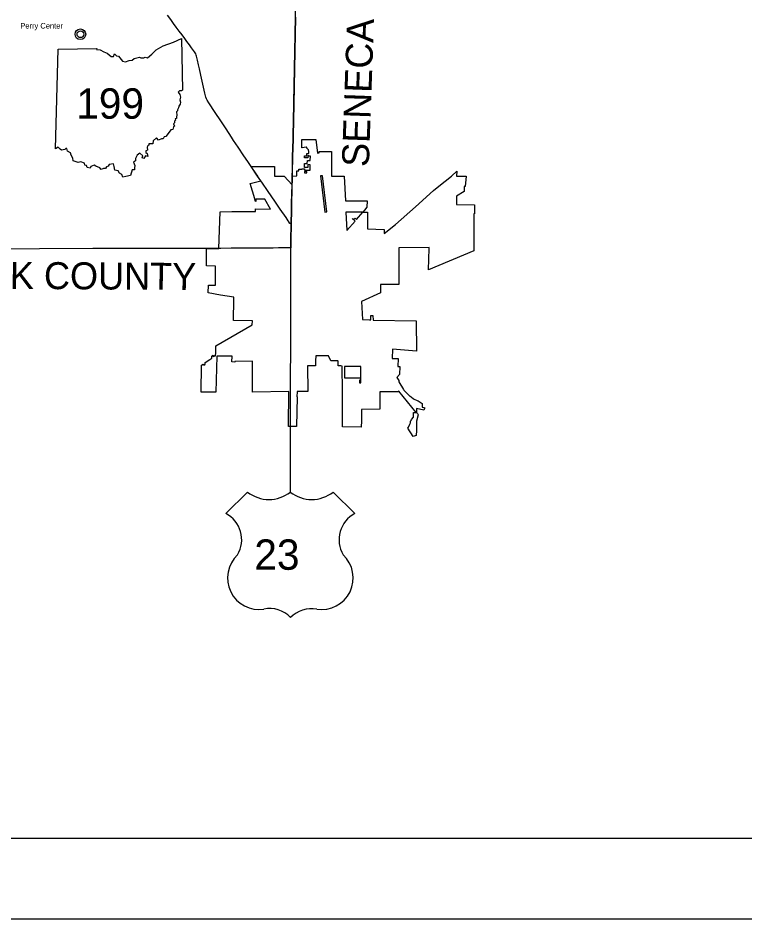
# Model space of a CAD drawing. Extents: x 0 to 851, y 0 to 440.
# Drawn here: x 384.3 to 474.6, y 0 to 111.8 of the extents above; entities that cross this region are included whole.
import ezdxf

# ---------------------------------------------------------------- set-up
doc = ezdxf.new("R2010")
doc.units = 0
for name, color, linetype in [('DV_X_Corp_Line', 7, 'Continuous'), ('GM_X_Adjacent_County_Text', 7, 'Continuous'), ('GM_X_County', 7, 'Continuous'), ('GM_X_State_Route', 7, 'Continuous'), ('GM_X_US_Route', 7, 'Continuous'), ('PV_P_Text', 7, 'Continuous'), ('SH_Border', 7, 'Continuous'), ('SH_Cut_Line', 7, 'Continuous')]:
    doc.layers.add(name, color=color, linetype=linetype)

msp = doc.modelspace()

# ---------------------------------------------------------------- linework, layer by layer
at = {"layer": 'DV_X_Corp_Line'}
for points in [[(435.4, 83.32), (431.64, 83.31), (431.61, 79.39), (431.61, 79.3), (431.6, 78.73), (430.65, 78.73), (429.86, 78.73), (429.36, 78.73), (429.36, 77.69), (427, 76.64), (427.09, 74.38), (427.98, 74.37), (428.13, 74.37), (428.16, 74.91), (428.39, 74.91), (428.43, 74.33), (433.77, 74.24), (433.81, 70.47), (430.83, 70.72), (430.8, 69.57), (431.52, 69.56), (431.51, 68.55), (431.74, 68.55), (431.72, 67.59), (431.36, 67.22), (431.61, 66.83), (431.61, 66.65), (432.2, 65.73), (432.25, 65.65), (432.64, 65.2), (432.76, 65.1), (432.88, 64.99), (432.95, 64.94), (433.01, 64.89), (433.15, 64.79), (433.46, 64.57), (433.53, 64.53), (433.6, 64.49), (433.8, 64.39), (433.96, 64.31), (434.02, 64.3), (434.53, 63.99), (434.52, 63.5), (434.53, 63.5), (434.54, 63.5), (434.72, 63.46), (434.86, 63.43), (434.84, 63.42), (434.82, 63.39), (434.79, 63.36), (434.76, 63.25), (434.74, 63.15), (434.74, 63.13), (433.83, 63.37), (433.82, 62.84), (433.94, 62.73), (434.04, 62.58), (433.81, 61.8), (433.8, 60.63), (433.79, 59.99), (433.54, 59.93), (433.4, 59.9), (432.74, 60.92), (432.81, 61.05), (433, 61.4), (433.07, 61.57), (433.08, 61.79), (433.16, 61.88), (433.21, 62), (433.44, 62.28), (433.43, 62.35), (433.43, 62.42), (433.42, 62.63), (433.43, 62.85), (433.78, 62.84), (431.61, 65.51), (431.51, 65.43), (429.24, 65.44), (429.25, 63.26), (426.97, 63.23), (426.97, 61.82), (426.96, 61.02), (424.61, 61.07), (424.63, 65.46), (424.59, 68.62), (424.42, 68.63), (424.09, 68.63), (424.09, 69.2), (424.08, 69.24), (424.05, 69.26), (424.02, 69.27), (423.16, 69.27), (422.89, 69.91), (422.57, 69.91), (421.3, 69.91), (421.29, 69.27), (421.29, 68.63), (420.27, 68.64), (420.3, 65.47), (419.67, 65.46), (418.98, 65.46), (418.95, 64.8), (418.99, 64.8), (418.92, 61.11), (417.91, 61.12), (417.95, 65.45), (413.44, 65.4), (413.44, 69.22), (411.24, 69.2), (411.24, 69.12), (410.9, 69.13), (410.91, 69.83), (409.04, 69.83), (408.89, 65.37), (407.09, 65.37), (407.1, 68.73), (407.31, 68.86), (407.4, 68.73), (407.58, 68.86), (407.57, 69.05), (408.16, 69.44), (408.16, 69.44), (408.39, 69.59), (408.38, 69.87), (408.54, 69.99), (408.54, 69.79), (408.75, 69.93), (408.75, 69.84), (408.86, 69.91), (408.88, 70.28), (408.89, 71.12), (413.42, 73.73), (413.44, 74.25), (411.11, 74.27), (411.14, 76.88), (411.14, 77.17), (409.47, 77.42), (407.94, 77.72), (407.97, 78.65), (408.85, 78.67), (408.86, 81.03), (407.74, 81.04), (407.75, 83.22), (409.25, 83.22), (409.44, 87.78), (410.87, 87.81), (410.89, 87.81), (413.82, 87.8), (413.84, 88.13), (415.68, 88.11), (414.99, 89.32), (413.86, 89.34), (413.86, 89.05), (413.8, 89.17), (413.72, 89.39), (413.14, 91.29), (414.47, 91.63), (414.09, 92.18), (413.27, 93.39), (416.18, 93.4), (416.17, 92.19), (416.5, 92.19), (417.37, 92.19), (418.36, 91.12), (418.39, 92.19), (418.96, 92.22), (418.97, 92.86), (419.22, 92.86), (419.22, 93.06), (419.59, 93.06), (419.59, 93.1), (419.9, 93.1), (419.89, 92.93), (420.61, 92.93), (420.62, 93.61), (420.32, 93.62), (420.31, 93.28), (420.21, 93.28), (419.9, 93.28), (419.9, 93.45), (419.91, 93.78), (420.25, 93.78), (420.26, 94.13), (420.63, 94.13), (420.64, 94.66), (420.46, 94.66), (420.46, 94.72), (420.33, 94.72), (420.33, 94.47), (419.92, 94.47), (419.92, 94.72), (420.21, 94.72), (420.21, 94.99), (420.21, 95), (420.42, 95), (420.43, 95.06), (420.43, 95.28), (420.4, 95.38), (420.39, 95.44), (420.36, 95.5), (420.26, 95.6), (420.21, 95.67), (420.18, 95.76), (420.17, 95.77), (420.16, 95.78), (420.16, 95.78), (420.13, 95.78), (420.1, 95.77), (419.63, 95.7), (419.57, 95.69), (419.58, 96.16), (419.58, 96.72), (420.39, 96.72), (421.32, 96.72), (421.53, 95.06), (421.74, 95.09), (421.71, 95.25), (423.24, 95.26), (423.25, 92.2), (424.82, 92.2), (425, 89.12), (427.67, 89.11), (427.66, 88.33), (427.37, 87.98), (427.14, 87.71), (427.71, 87.71), (427.71, 85.64), (429.8, 85.57), (429.81, 85.06), (431.2, 86.2), (433.68, 88.4), (435.94, 90.39), (436.58, 90.96), (438.16, 92.19), (438.83, 92.83), (438.77, 92.19), (439.96, 92.18), (439.87, 90.91), (439.74, 90.9), (439.72, 90.29), (438.79, 89.69), (438.78, 88.67), (441.02, 88.64), (441.02, 87.51), (440.95, 87.51), (440.94, 83.2), (440.94, 82.94), (435.31, 80.56), (435.4, 83.23)], [(419.89, 92.59), (420.2, 92.59), (420.2, 92.77), (419.9, 92.76)], [(421.9, 92.22), (422.42, 87.73), (422.7, 87.75), (422.15, 92.21)], [(425.04, 87.74), (425.16, 85.45), (426.2, 86.6), (425.83, 86.94), (426.07, 86.84), (426.18, 86.97), (426.37, 86.82), (427.13, 87.71)], [(424.87, 67.15), (426.84, 67.14), (426.84, 66.89), (426.72, 66.89), (426.72, 66.55), (426.91, 66.55), (426.92, 68.56), (424.88, 68.57)]]:
    msp.add_lwpolyline(points, close=True, dxfattribs=at)
for radius in [0.658, 0.417]:
    msp.add_circle((392.08, 109.8), radius, dxfattribs=at)
at = {"layer": 'GM_X_County'}
msp.add_lwpolyline([(418.78, 111.94), (418.65, 105.56), (418.65, 105.5), (418.58, 101.12), (418.58, 101.07), (418.44, 95.23), (418.43, 95.03), (418.39, 92.19), (418.31, 88.84), (418.3, 88.33), (418.29, 87.77), (418.28, 87.39), (418.27, 86.86), (418.26, 86.4), (418.26, 86.34), (418.25, 86.1), (418.24, 85.54), (418.23, 84.95), (418.23, 83.31), (417.4, 83.31), (416.67, 83.3), (416.03, 83.25), (413.74, 83.25), (410.82, 83.25), (409.52, 83.22), (407.75, 83.22), (397.98, 83.22), (393.82, 83.21), (393.63, 83.21), (387, 83.16), (383.38, 83.14)], dxfattribs=at)
at = {"layer": 'GM_X_State_Route'}
for points in [[(411.09, 96.63), (410.84, 97.02), (410.16, 98.05), (409.5, 99.06), (408.8, 100.11), (408.04, 101.28), (407.82, 101.61), (407.72, 101.8), (407.64, 102), (407.53, 102.5), (407.28, 103.6), (407.04, 104.72), (406.86, 105.53), (406.75, 106.02), (406.62, 106.6), (406.5, 107.07), (406.46, 107.22), (406.4, 107.36), (406.33, 107.49), (406.24, 107.62), (406.12, 107.79), (405.88, 108.11), (405.61, 108.49), (405.3, 108.9), (405.03, 109.27), (404.7, 109.72), (404.34, 110.2), (403.99, 110.67), (403.64, 111.14), (403.29, 111.62), (402.91, 112.15)], [(413.36, 93.28), (413.21, 93.5), (412.85, 94.01), (412.37, 94.72), (411.65, 95.79), (411.09, 96.63)], [(414.49, 91.6), (414.19, 92.04), (414.1, 92.19), (413.81, 92.61), (413.36, 93.28)], [(418.01, 86.45), (418, 86.46), (417.87, 86.64), (417.61, 87.05), (416.88, 88.11), (416.3, 88.98), (415.32, 90.41), (414.7, 91.3), (414.49, 91.6)], [(418.26, 86.4), (418.17, 86.31), (418.08, 86.33), (418.01, 86.45)]]:
    msp.add_lwpolyline(points, dxfattribs=at)
at = {"layer": 'GM_X_US_Route'}
for points in [[(418.58, 101.34), (418.65, 105.5), (418.65, 105.56), (418.78, 111.94), (418.83, 114.37), (418.83, 114.49), (418.93, 118.8), (419.03, 123.4), (419.11, 127.67)], [(418.43, 95.05), (418.44, 95.23), (418.58, 101.07)], [(418.58, 101.07), (418.58, 101.12), (418.58, 101.34)], [(418.4, 92.91), (418.43, 95.03), (418.43, 95.05)], [(418.39, 92.28), (418.4, 92.91)], [(418.36, 91.12), (418.39, 92.19), (418.39, 92.28)], [(418.26, 86.4), (418.27, 86.86), (418.28, 87.39), (418.29, 87.77), (418.3, 88.33), (418.31, 88.84), (418.36, 91.12)], [(418.25, 86.05), (418.25, 86.1), (418.26, 86.34), (418.26, 86.4)], [(418.15, 52.99), (418.23, 84.95), (418.24, 85.54), (418.25, 86.05)]]:
    msp.add_lwpolyline(points, dxfattribs=at)
at = {"layer": 'PV_P_Text'}
for p, q in [((389, 95.59), (389.34, 107.97)), ((389, 95.59), (389.34, 107.97)), ((412.83, 52.99), (410.15, 50.31)), ((412.83, 52.99), (410.15, 50.31)), ((426.15, 50.31), (423.47, 52.99)), ((426.15, 50.31), (423.47, 52.99))]:
    msp.add_line(p, q, dxfattribs=at)
for points in [[(389.34, 107.97), (394.14, 108.05), (394.07, 107.9), (394.52, 107.87), (395, 107.6), (395.41, 107.44), (395.91, 107.04), (396.21, 107.05), (396.33, 107.37), (396.56, 107.12), (396.83, 107.08), (397.3, 106.48), (397.68, 106.36), (398.15, 106.56), (398.49, 106.59), (398.75, 106.79), (399.4, 106.96), (399.59, 106.86), (399.94, 106.88), (400.11, 106.96), (400.42, 106.89), (400.95, 107.34), (401.5, 107.87), (402.35, 108.37), (403.62, 108.84), (404.62, 109.27), (404.76, 102.85)], [(389.34, 107.97), (394.14, 108.05), (394.07, 107.9), (394.52, 107.87), (395, 107.6), (395.41, 107.44), (395.91, 107.04), (396.21, 107.05), (396.33, 107.37), (396.56, 107.12), (396.83, 107.08), (397.3, 106.48), (397.68, 106.36), (398.15, 106.56), (398.49, 106.59), (398.75, 106.79), (399.4, 106.96), (399.59, 106.86), (399.94, 106.88), (400.11, 106.96), (400.42, 106.89), (400.95, 107.34), (401.5, 107.87), (402.35, 108.37), (403.62, 108.84), (404.62, 109.27), (404.76, 102.85)], [(404.76, 102.85), (404.62, 102.76), (404.39, 102.8), (404.23, 102.62), (404.42, 102.32), (404.51, 102), (404.43, 101.65), (404.51, 101.36), (404.46, 101.12), (404.31, 100.88), (404.26, 100.65), (404.14, 100.41), (404.15, 100.28), (404.03, 100.17), (404.05, 99.77), (404, 99.55), (404.02, 99.35), (403.83, 99.3), (403.87, 99.14), (403.75, 99.02), (403.77, 98.81), (403.64, 98.68), (403.77, 98.41), (403.66, 98.32), (403.57, 97.99), (403.33, 97.93), (402.84, 97.33), (402.67, 97.1), (402.48, 97.05), (402.37, 96.81), (402.13, 96.81), (401.77, 96.65), (401.54, 96.93), (401.13, 96.59), (401.08, 96.21), (400.57, 96.22), (400.59, 96.03), (400.47, 95.97), (400.37, 95.77), (400.43, 95.43), (400.19, 95.34), (400.21, 95.14), (400.37, 95.01), (400.44, 94.63), (400.18, 94.71), (399.97, 94.38), (399.75, 94.46), (399.83, 94.73), (399.46, 95.06), (399.11, 94.8), (398.93, 94.38), (398.93, 94.09), (398.67, 93.92), (398.84, 93.52), (398.81, 93.24), (398.81, 92.98), (398.49, 92.98), (398.3, 92.27)], [(404.76, 102.85), (404.62, 102.76), (404.39, 102.8), (404.23, 102.62), (404.42, 102.32), (404.51, 102), (404.43, 101.65), (404.51, 101.36), (404.46, 101.12), (404.31, 100.88), (404.26, 100.65), (404.14, 100.41), (404.15, 100.28), (404.03, 100.17), (404.05, 99.77), (404, 99.55), (404.02, 99.35), (403.83, 99.3), (403.87, 99.14), (403.75, 99.02), (403.77, 98.81), (403.64, 98.68), (403.77, 98.41), (403.66, 98.32), (403.57, 97.99), (403.33, 97.93), (402.84, 97.33), (402.67, 97.1), (402.48, 97.05), (402.37, 96.81), (402.13, 96.81), (401.77, 96.65), (401.54, 96.93), (401.13, 96.59), (401.08, 96.21), (400.57, 96.22), (400.59, 96.03), (400.47, 95.97), (400.37, 95.77), (400.43, 95.43), (400.19, 95.34), (400.21, 95.14), (400.37, 95.01), (400.44, 94.63), (400.18, 94.71), (399.97, 94.38), (399.75, 94.46), (399.83, 94.73), (399.46, 95.06), (399.11, 94.8), (398.93, 94.38), (398.93, 94.09), (398.67, 93.92), (398.84, 93.52), (398.81, 93.24), (398.81, 92.98), (398.49, 92.98), (398.3, 92.27)], [(398.3, 92.27), (397.74, 92.14), (397.35, 92.06), (397.21, 92.38), (396.93, 92.55), (396.75, 92.87), (396.35, 92.92), (396.26, 93.37), (396.21, 93.73), (395.67, 93.64), (395.52, 93.42), (395.32, 93.36), (395.21, 93.13), (394.95, 93.12), (394.66, 93.01), (394.48, 93.23), (394.01, 93.45), (393.81, 93.56), (393.37, 93.39), (393.28, 93.18), (392.93, 93.27), (392.85, 93.5), (392.64, 93.57), (392.59, 93.82), (392.14, 93.95), (391.8, 93.9), (391.19, 94.1), (391.15, 94.42), (390.95, 94.81), (390.84, 95.09), (390.46, 95.3), (390.38, 95.62), (390.26, 95.61), (390.15, 95.48), (389.72, 95.42), (389.55, 95.56), (389.31, 95.78), (389, 95.59)], [(398.3, 92.27), (397.74, 92.14), (397.35, 92.06), (397.21, 92.38), (396.93, 92.55), (396.75, 92.87), (396.35, 92.92), (396.26, 93.37), (396.21, 93.73), (395.67, 93.64), (395.52, 93.42), (395.32, 93.36), (395.21, 93.13), (394.95, 93.12), (394.66, 93.01), (394.48, 93.23), (394.01, 93.45), (393.81, 93.56), (393.37, 93.39), (393.28, 93.18), (392.93, 93.27), (392.85, 93.5), (392.64, 93.57), (392.59, 93.82), (392.14, 93.95), (391.8, 93.9), (391.19, 94.1), (391.15, 94.42), (390.95, 94.81), (390.84, 95.09), (390.46, 95.3), (390.38, 95.62), (390.26, 95.61), (390.15, 95.48), (389.72, 95.42), (389.55, 95.56), (389.31, 95.78), (389, 95.59)]]:
    msp.add_lwpolyline(points, dxfattribs=at)
for centre, radius, start, end in [((415.49, 56.37), 4.31, 231.813, 308.187), ((415.49, 56.37), 4.31, 231.813, 308.187), ((420.81, 56.37), 4.31, 231.813, 308.187), ((420.81, 56.37), 4.31, 231.813, 308.187), ((408.47, 47.08), 3.64, 329.1175, 62.6108), ((408.47, 47.08), 3.64, 329.1175, 62.6108), ((427.83, 47.08), 3.64, 117.3892, 210.8825), ((427.83, 47.08), 3.64, 117.3892, 210.8825), ((414.28, 42.33), 3.93, 133.0046, 278.7282), ((414.28, 42.33), 3.93, 133.0046, 278.7282), ((422.02, 42.33), 3.93, 261.2718, 46.9954), ((422.02, 42.33), 3.93, 261.2718, 46.9954), ((415.6, 35.01), 3.52, 43.4177, 101.8742), ((415.6, 35.01), 3.52, 43.4177, 101.8742), ((420.78, 34.77), 3.73, 79.9613, 134.7468), ((420.78, 34.77), 3.73, 79.9613, 134.7468)]:
    msp.add_arc(centre, radius, start, end, dxfattribs=at)
at = {"layer": 'SH_Border'}
msp.add_lwpolyline([(30, 430), (670, 430), (670, 10), (30, 10)], close=True, dxfattribs=at)
at = {"layer": 'SH_Cut_Line'}
msp.add_lwpolyline([(0, 0), (680, 0), (680, 440), (0, 440)], close=True, dxfattribs=at)

# ---------------------------------------------------------------- texts
at = {"layer": 'DV_X_Corp_Line'}
msp.add_text('Perry Center', height=0.6979, rotation=0, dxfattribs=at).set_placement((384.62, 110.51))
at = {"layer": 'GM_X_Adjacent_County_Text'}
for s, rotation, p in [('SENECA COUNTY', 87.9748, (427.89, 93.29)), ('HANCOCK COUNTY', 359.6476, (363.9, 78.32))]:
    msp.add_text(s, height=3.35, rotation=rotation, dxfattribs=at).set_placement(p)
at = {"layer": 'PV_P_Text'}
for s, p in [('199', (391.57, 99.32)), ('23', (413.68, 43.34))]:
    msp.add_text(s, height=3.769, dxfattribs=at).set_placement(p)

doc.saveas('drawing.dxf')
